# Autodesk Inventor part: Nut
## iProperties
Shininess: 20.0
Length Units: 11269
Angle Units: 11279
Time Units: 11290
Mass Units: 11283
Length Display Precision: 3
Angle Display Precision: 2
Created: 2002-01
Part Number: Nut
Document SubType Name: Modeling
Designer: ***
Density: 0.0
Volumn: 0.0
Area: 0.0
PropertySet Name: Model Information
Control State: 0
Master: False
Checked Out: False
Author: ***
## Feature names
1. Extrusion1
2. Fillet1
3. Extrusion2
